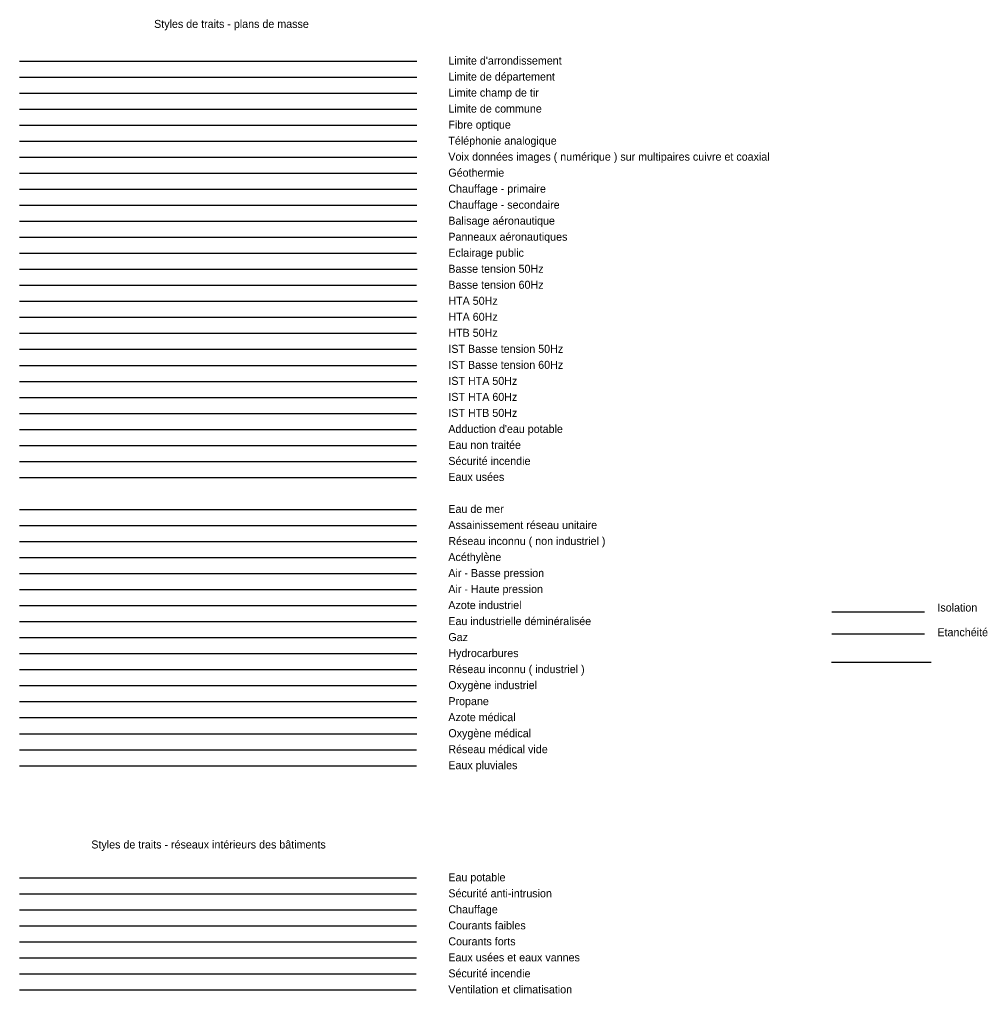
# Model space of a CAD drawing. Extents: x 3494.1 to 3554.6, y -18944.5 to -18883.7.
import ezdxf

# ---------------------------------------------------------------- set-up
doc = ezdxf.new("R2010")
doc.units = 0
for name, color, linetype in [('GO_COUVERTURE', 7, 'Continuous'), ('LIM_ADM ARRONDISSEMENT', 7, 'Continuous'), ('LIM_ADM DEPARTEMENT', 7, 'Continuous'), ('LIM_ADM_CHAMP TIR', 7, 'Continuous'), ('LIM_ADM_COMMUNE', 7, 'Continuous'), ('R_CF_FO_CANALISATION_CL_C', 7, 'Continuous'), ('R_CF_TEL_LIAISON_CL_C', 7, 'Continuous'), ('R_CF_VDI_LIAISON_CL_C', 7, 'Continuous'), ('R_CH_GEOTHERMIE_CANALISATION_CL_C', 7, 'Continuous'), ('R_CH_PRIM_CANALISATION_CL_C', 7, 'Continuous'), ('R_CH_SECOND_CANALISATION_CL_C', 7, 'Continuous'), ('R_ECLAIR_AERO_LIAISON_CL_C', 7, 'Continuous'), ('R_ECLAIR_PANNEAU_AERO_LIAISON_CL_C', 7, 'Continuous'), ('R_ECLAIR_PUB_LIAISON_CL_C', 7, 'Continuous'), ('R_ELEC_BT_50HZ_LIAISON_CL_C', 7, 'Continuous'), ('R_ELEC_BT_60HZ_LIAISON_CL_C', 7, 'Continuous'), ('R_ELEC_HTA_50HZ_LIAISON_CL_C', 7, 'Continuous'), ('R_ELEC_HTA_60HZ_LIAISON_CL_C', 7, 'Continuous'), ('R_ELEC_HTB_50HZ_LIAISON_CL_C', 7, 'Continuous'), ('R_ELEC_IST_BT_50HZ_LIAISON_CL_C', 7, 'Continuous'), ('R_ELEC_IST_BT_60HZ_LIAISON_CL_C', 7, 'Continuous'), ('R_ELEC_IST_HTA_50HZ_LIAISON_CL_C', 7, 'Continuous'), ('R_ELEC_IST_HTA_60HZ_LIAISON_CL_C', 7, 'Continuous'), ('R_ELEC_IST_HTB_50HZ_LIAISON_CL_C', 7, 'Continuous'), ('R_EPR_AEP_CANALISATION_CL_C', 7, 'Continuous'), ('R_EPR_EAU_NON_TRAITEE_CANALISATION_CL_C', 7, 'Continuous'), ('R_EPR_INCENDIE_CANALISATION_CL_C', 7, 'Continuous'), ('R_ES_EU_CANALISATION_CL_C', 7, 'Continuous'), ('R_ES_MER_CANALISATION_CL_C', 7, 'Continuous'), ('R_ES_UNITAIRE_CANALISATION_CL_C', 7, 'Continuous'), ('R_INCONNU_CANALISATION_CL_C', 7, 'Continuous'), ('R_IND_ACETYLENE_CANALISATION_CL_C', 7, 'Continuous'), ('R_IND_AIR_BP_CANALISATION_CL_C', 7, 'Continuous'), ('R_IND_AIR_HP_CANALISATION_CL_C', 7, 'Continuous'), ('R_IND_AZOTE_CANALISATION_CL_C', 7, 'Continuous'), ('R_IND_EAU_DEMINERALISEE_CANALISATION_CL_C', 7, 'Continuous'), ('R_IND_GAZ_NAT_CANALISATION_CL_C', 7, 'Continuous'), ('R_IND_HYDROCARBURE_CANALISATION_CL_C', 7, 'Continuous'), ('R_IND_INDUS_INCON_CANALISATION_CL_C', 7, 'Continuous'), ('R_IND_OXYGENE_CANALISATION_CL_C', 7, 'Continuous'), ('R_IND_PROPANE_CANALISATION_CL_C', 7, 'Continuous'), ('R_MED_AZOTE_CANALISATION_CL_C', 7, 'Continuous'), ('R_MED_OXYGENE_CANALISATION_CL_C', 7, 'Continuous'), ('R_MED_VIDE_CANALISATION_CL_C', 7, 'Continuous'), ('R_PLU_CANALISATION_CL_C', 7, 'Continuous'), ('SO_AEP_LIAISON', 7, 'Continuous'), ('SO_ANTI_INTRUSION_LIAISON', 7, 'Continuous'), ('SO_CHAUFFAGE_LIAISON', 7, 'Continuous'), ('SO_ELEC_C_FAIBLES_LIAISON', 7, 'Continuous'), ('SO_ELEC_C_FORTS_LIAISON', 7, 'Continuous'), ('SO_EU_EV_LIAISON', 7, 'Continuous'), ('SO_ISOLATION', 7, 'Continuous'), ('SO_SECU_INCENDIE_LIAISON', 7, 'Continuous'), ('SO_VMC_CVC_CTA_RES-TEXTE', 7, 'Continuous'), ('VOIRIE_VOIES FERREES', 7, 'Continuous')]:
    doc.layers.add(name, color=color, linetype=linetype)

msp = doc.modelspace()

# ---------------------------------------------------------------- linework, layer by layer
at = {"layer": 'GO_COUVERTURE'}
msp.add_line((3544.844, -18922.069), (3550.637, -18922.069), dxfattribs=at)
at = {"layer": 'LIM_ADM ARRONDISSEMENT'}
msp.add_line((3494.112, -18886.308), (3518.932, -18886.308), dxfattribs=at)
at = {"layer": 'LIM_ADM DEPARTEMENT'}
msp.add_line((3494.112, -18887.308), (3518.932, -18887.308), dxfattribs=at)
at = {"layer": 'LIM_ADM_CHAMP TIR'}
msp.add_line((3494.112, -18888.308), (3518.932, -18888.308), dxfattribs=at)
at = {"layer": 'LIM_ADM_COMMUNE'}
msp.add_line((3494.112, -18889.308), (3518.932, -18889.308), dxfattribs=at)
at = {"layer": 'R_CF_FO_CANALISATION_CL_C'}
msp.add_line((3494.112, -18890.308), (3518.932, -18890.308), dxfattribs=at)
at = {"layer": 'R_CF_TEL_LIAISON_CL_C'}
msp.add_line((3494.112, -18891.308), (3518.932, -18891.308), dxfattribs=at)
at = {"layer": 'R_CF_VDI_LIAISON_CL_C'}
msp.add_line((3494.112, -18892.308), (3518.932, -18892.308), dxfattribs=at)
at = {"layer": 'R_CH_GEOTHERMIE_CANALISATION_CL_C'}
msp.add_line((3494.112, -18893.308), (3518.932, -18893.308), dxfattribs=at)
at = {"layer": 'R_CH_PRIM_CANALISATION_CL_C'}
msp.add_line((3494.112, -18894.308), (3518.932, -18894.308), dxfattribs=at)
at = {"layer": 'R_CH_SECOND_CANALISATION_CL_C'}
msp.add_line((3494.112, -18895.308), (3518.932, -18895.308), dxfattribs=at)
at = {"layer": 'R_ECLAIR_AERO_LIAISON_CL_C'}
msp.add_line((3494.112, -18896.308), (3518.932, -18896.308), dxfattribs=at)
at = {"layer": 'R_ECLAIR_PANNEAU_AERO_LIAISON_CL_C'}
msp.add_line((3494.112, -18897.308), (3518.932, -18897.308), dxfattribs=at)
at = {"layer": 'R_ECLAIR_PUB_LIAISON_CL_C'}
msp.add_line((3494.112, -18898.308), (3518.912, -18898.308), dxfattribs=at)
at = {"layer": 'R_ELEC_BT_50HZ_LIAISON_CL_C'}
msp.add_line((3494.112, -18899.308), (3518.942, -18899.308), dxfattribs=at)
at = {"layer": 'R_ELEC_BT_60HZ_LIAISON_CL_C'}
msp.add_line((3494.112, -18900.308), (3518.905, -18900.308), dxfattribs=at)
at = {"layer": 'R_ELEC_HTA_50HZ_LIAISON_CL_C'}
msp.add_line((3494.112, -18901.308), (3518.95, -18901.308), dxfattribs=at)
at = {"layer": 'R_ELEC_HTA_60HZ_LIAISON_CL_C'}
msp.add_line((3494.112, -18902.308), (3518.905, -18902.308), dxfattribs=at)
at = {"layer": 'R_ELEC_HTB_50HZ_LIAISON_CL_C'}
msp.add_line((3494.112, -18903.304), (3518.905, -18903.304), dxfattribs=at)
at = {"layer": 'R_ELEC_IST_BT_50HZ_LIAISON_CL_C'}
msp.add_line((3494.112, -18904.308), (3518.897, -18904.308), dxfattribs=at)
at = {"layer": 'R_ELEC_IST_BT_60HZ_LIAISON_CL_C'}
msp.add_line((3494.112, -18905.308), (3518.912, -18905.308), dxfattribs=at)
at = {"layer": 'R_ELEC_IST_HTA_50HZ_LIAISON_CL_C'}
msp.add_line((3494.112, -18906.308), (3518.927, -18906.308), dxfattribs=at)
at = {"layer": 'R_ELEC_IST_HTA_60HZ_LIAISON_CL_C'}
msp.add_line((3494.112, -18907.308), (3518.927, -18907.308), dxfattribs=at)
at = {"layer": 'R_ELEC_IST_HTB_50HZ_LIAISON_CL_C'}
msp.add_line((3494.112, -18908.308), (3518.897, -18908.308), dxfattribs=at)
at = {"layer": 'R_EPR_AEP_CANALISATION_CL_C'}
msp.add_line((3494.112, -18909.308), (3518.897, -18909.308), dxfattribs=at)
at = {"layer": 'R_EPR_EAU_NON_TRAITEE_CANALISATION_CL_C'}
msp.add_line((3494.112, -18910.308), (3518.912, -18910.308), dxfattribs=at)
at = {"layer": 'R_EPR_INCENDIE_CANALISATION_CL_C'}
msp.add_line((3494.112, -18911.308), (3518.912, -18911.308), dxfattribs=at)
at = {"layer": 'R_ES_EU_CANALISATION_CL_C'}
msp.add_line((3494.112, -18912.308), (3518.897, -18912.308), dxfattribs=at)
at = {"layer": 'R_ES_MER_CANALISATION_CL_C'}
msp.add_line((3494.112, -18914.308), (3518.912, -18914.308), dxfattribs=at)
at = {"layer": 'R_ES_UNITAIRE_CANALISATION_CL_C'}
msp.add_line((3494.112, -18915.308), (3518.897, -18915.308), dxfattribs=at)
at = {"layer": 'R_INCONNU_CANALISATION_CL_C'}
msp.add_line((3494.112, -18916.308), (3518.927, -18916.308), dxfattribs=at)
at = {"layer": 'R_IND_ACETYLENE_CANALISATION_CL_C'}
msp.add_line((3494.112, -18917.308), (3518.883, -18917.308), dxfattribs=at)
at = {"layer": 'R_IND_AIR_BP_CANALISATION_CL_C'}
msp.add_line((3494.112, -18918.308), (3518.897, -18918.308), dxfattribs=at)
at = {"layer": 'R_IND_AIR_HP_CANALISATION_CL_C'}
msp.add_line((3494.112, -18919.308), (3518.912, -18919.308), dxfattribs=at)
at = {"layer": 'R_IND_AZOTE_CANALISATION_CL_C'}
msp.add_line((3494.112, -18920.308), (3518.912, -18920.308), dxfattribs=at)
at = {"layer": 'R_IND_EAU_DEMINERALISEE_CANALISATION_CL_C'}
msp.add_line((3494.112, -18921.308), (3518.912, -18921.308), dxfattribs=at)
at = {"layer": 'R_IND_GAZ_NAT_CANALISATION_CL_C'}
msp.add_line((3494.112, -18922.308), (3518.912, -18922.308), dxfattribs=at)
at = {"layer": 'R_IND_HYDROCARBURE_CANALISATION_CL_C'}
msp.add_line((3494.112, -18923.308), (3518.927, -18923.308), dxfattribs=at)
at = {"layer": 'R_IND_INDUS_INCON_CANALISATION_CL_C'}
msp.add_line((3494.112, -18924.308), (3518.927, -18924.308), dxfattribs=at)
at = {"layer": 'R_IND_OXYGENE_CANALISATION_CL_C'}
msp.add_line((3494.112, -18925.308), (3518.897, -18925.308), dxfattribs=at)
at = {"layer": 'R_IND_PROPANE_CANALISATION_CL_C'}
msp.add_line((3494.112, -18926.308), (3518.897, -18926.308), dxfattribs=at)
at = {"layer": 'R_MED_AZOTE_CANALISATION_CL_C'}
msp.add_line((3494.112, -18927.308), (3518.927, -18927.308), dxfattribs=at)
at = {"layer": 'R_MED_OXYGENE_CANALISATION_CL_C'}
msp.add_line((3494.112, -18928.308), (3518.927, -18928.308), dxfattribs=at)
at = {"layer": 'R_MED_VIDE_CANALISATION_CL_C'}
msp.add_line((3494.112, -18929.308), (3518.912, -18929.308), dxfattribs=at)
at = {"layer": 'R_PLU_CANALISATION_CL_C'}
msp.add_line((3494.112, -18930.308), (3518.912, -18930.308), dxfattribs=at)
at = {"layer": 'SO_AEP_LIAISON'}
msp.add_line((3494.112, -18937.308), (3518.912, -18937.308), dxfattribs=at)
at = {"layer": 'SO_ANTI_INTRUSION_LIAISON'}
msp.add_line((3494.112, -18938.308), (3518.912, -18938.308), dxfattribs=at)
at = {"layer": 'SO_CHAUFFAGE_LIAISON'}
msp.add_line((3494.112, -18939.308), (3518.912, -18939.308), dxfattribs=at)
at = {"layer": 'SO_ELEC_C_FAIBLES_LIAISON'}
msp.add_line((3494.112, -18940.308), (3518.912, -18940.308), dxfattribs=at)
at = {"layer": 'SO_ELEC_C_FORTS_LIAISON'}
msp.add_line((3494.112, -18941.308), (3518.897, -18941.308), dxfattribs=at)
at = {"layer": 'SO_EU_EV_LIAISON'}
msp.add_line((3494.112, -18942.308), (3518.897, -18942.308), dxfattribs=at)
at = {"layer": 'SO_ISOLATION'}
msp.add_line((3544.844, -18920.705), (3550.637, -18920.705), dxfattribs=at)
at = {"layer": 'SO_SECU_INCENDIE_LIAISON'}
msp.add_line((3494.112, -18943.308), (3518.883, -18943.308), dxfattribs=at)
at = {"layer": 'SO_VMC_CVC_CTA_RES-TEXTE'}
msp.add_line((3494.112, -18944.308), (3518.883, -18944.308), dxfattribs=at)
at = {"layer": 'VOIRIE_VOIES FERREES'}
msp.add_line((3544.823, -18923.85), (3551.054, -18923.85), dxfattribs=at)

# ---------------------------------------------------------------- texts
at = {"layer": 'GO_COUVERTURE'}
msp.add_text('Etanchéité', height=0.5, dxfattribs=at).set_placement((3551.437, -18922.223))
at = {"layer": 'LIM_ADM ARRONDISSEMENT'}
msp.add_text("Limite d'arrondissement", height=0.5, dxfattribs=at).set_placement((3520.895, -18886.527))
at = {"layer": 'LIM_ADM DEPARTEMENT'}
msp.add_text('Limite de département', height=0.5, dxfattribs=at).set_placement((3520.895, -18887.527))
at = {"layer": 'LIM_ADM_CHAMP TIR'}
msp.add_text('Limite champ de tir', height=0.5, dxfattribs=at).set_placement((3520.895, -18888.527))
at = {"layer": 'LIM_ADM_COMMUNE'}
msp.add_text('Limite de commune', height=0.5, dxfattribs=at).set_placement((3520.895, -18889.527))
at = {"layer": 'R_CF_FO_CANALISATION_CL_C'}
msp.add_text('Fibre optique', height=0.5, dxfattribs=at).set_placement((3520.895, -18890.527))
at = {"layer": 'R_CF_TEL_LIAISON_CL_C'}
msp.add_text('Téléphonie analogique', height=0.5, dxfattribs=at).set_placement((3520.895, -18891.527))
at = {"layer": 'R_CF_VDI_LIAISON_CL_C'}
msp.add_text('Voix données images ( numérique ) sur multipaires cuivre et coaxial', height=0.5, dxfattribs=at).set_placement((3520.895, -18892.527))
at = {"layer": 'R_CH_GEOTHERMIE_CANALISATION_CL_C'}
msp.add_text('Géothermie', height=0.5, dxfattribs=at).set_placement((3520.895, -18893.527))
at = {"layer": 'R_CH_PRIM_CANALISATION_CL_C'}
msp.add_text('Chauffage - primaire', height=0.5, dxfattribs=at).set_placement((3520.895, -18894.527))
at = {"layer": 'R_CH_SECOND_CANALISATION_CL_C'}
msp.add_text('Chauffage - secondaire ', height=0.5, dxfattribs=at).set_placement((3520.895, -18895.527))
at = {"layer": 'R_ECLAIR_AERO_LIAISON_CL_C'}
msp.add_text('Balisage aéronautique', height=0.5, dxfattribs=at).set_placement((3520.895, -18896.527))
at = {"layer": 'R_ECLAIR_PANNEAU_AERO_LIAISON_CL_C'}
msp.add_text('Panneaux aéronautiques', height=0.5, dxfattribs=at).set_placement((3520.895, -18897.527))
at = {"layer": 'R_ECLAIR_PUB_LIAISON_CL_C'}
msp.add_text('Eclairage public', height=0.5, dxfattribs=at).set_placement((3520.895, -18898.527))
at = {"layer": 'R_ELEC_BT_50HZ_LIAISON_CL_C'}
msp.add_text('Basse tension 50Hz', height=0.5, dxfattribs=at).set_placement((3520.895, -18899.527))
at = {"layer": 'R_ELEC_BT_60HZ_LIAISON_CL_C'}
msp.add_text('Basse tension 60Hz', height=0.5, dxfattribs=at).set_placement((3520.895, -18900.527))
at = {"layer": 'R_ELEC_HTA_50HZ_LIAISON_CL_C'}
msp.add_text('HTA 50Hz', height=0.5, dxfattribs=at).set_placement((3520.895, -18901.527))
at = {"layer": 'R_ELEC_HTA_60HZ_LIAISON_CL_C'}
msp.add_text('HTA 60Hz', height=0.5, dxfattribs=at).set_placement((3520.895, -18902.527))
at = {"layer": 'R_ELEC_HTB_50HZ_LIAISON_CL_C'}
msp.add_text('HTB 50Hz', height=0.5, dxfattribs=at).set_placement((3520.895, -18903.527))
at = {"layer": 'R_ELEC_IST_BT_50HZ_LIAISON_CL_C'}
msp.add_text('IST Basse tension 50Hz', height=0.5, dxfattribs=at).set_placement((3520.895, -18904.527))
at = {"layer": 'R_ELEC_IST_BT_60HZ_LIAISON_CL_C'}
msp.add_text('IST Basse tension 60Hz', height=0.5, dxfattribs=at).set_placement((3520.895, -18905.527))
at = {"layer": 'R_ELEC_IST_HTA_50HZ_LIAISON_CL_C'}
msp.add_text('IST HTA 50Hz', height=0.5, dxfattribs=at).set_placement((3520.895, -18906.527))
at = {"layer": 'R_ELEC_IST_HTA_60HZ_LIAISON_CL_C'}
msp.add_text('IST HTA 60Hz', height=0.5, dxfattribs=at).set_placement((3520.895, -18907.527))
at = {"layer": 'R_ELEC_IST_HTB_50HZ_LIAISON_CL_C'}
msp.add_text('IST HTB 50Hz', height=0.5, dxfattribs=at).set_placement((3520.895, -18908.527))
at = {"layer": 'R_EPR_AEP_CANALISATION_CL_C'}
msp.add_text("Adduction d'eau potable ", height=0.5, dxfattribs=at).set_placement((3520.895, -18909.527))
at = {"layer": 'R_EPR_EAU_NON_TRAITEE_CANALISATION_CL_C'}
msp.add_text('Eau non traitée', height=0.5, dxfattribs=at).set_placement((3520.895, -18910.527))
at = {"layer": 'R_EPR_INCENDIE_CANALISATION_CL_C'}
msp.add_text('Sécurité incendie', height=0.5, dxfattribs=at).set_placement((3520.895, -18911.527))
at = {"layer": 'R_ES_EU_CANALISATION_CL_C'}
msp.add_text('Eaux usées', height=0.5, dxfattribs=at).set_placement((3520.895, -18912.527))
at = {"layer": 'R_ES_MER_CANALISATION_CL_C'}
msp.add_text('Eau de mer', height=0.5, dxfattribs=at).set_placement((3520.895, -18914.527))
at = {"layer": 'R_ES_UNITAIRE_CANALISATION_CL_C'}
msp.add_text('Assainissement réseau unitaire', height=0.5, dxfattribs=at).set_placement((3520.895, -18915.527))
at = {"layer": 'R_INCONNU_CANALISATION_CL_C'}
msp.add_text('Réseau inconnu ( non industriel )', height=0.5, dxfattribs=at).set_placement((3520.895, -18916.527))
at = {"layer": 'R_IND_ACETYLENE_CANALISATION_CL_C'}
msp.add_text('Acéthylène', height=0.5, dxfattribs=at).set_placement((3520.895, -18917.527))
at = {"layer": 'R_IND_AIR_BP_CANALISATION_CL_C'}
msp.add_text('Air - Basse pression', height=0.5, dxfattribs=at).set_placement((3520.895, -18918.527))
at = {"layer": 'R_IND_AIR_HP_CANALISATION_CL_C'}
msp.add_text('Air - Haute pression', height=0.5, dxfattribs=at).set_placement((3520.895, -18919.527))
at = {"layer": 'R_IND_AZOTE_CANALISATION_CL_C'}
msp.add_text('Azote industriel', height=0.5, dxfattribs=at).set_placement((3520.895, -18920.527))
at = {"layer": 'R_IND_EAU_DEMINERALISEE_CANALISATION_CL_C'}
msp.add_text('Eau industrielle déminéralisée', height=0.5, dxfattribs=at).set_placement((3520.895, -18921.527))
at = {"layer": 'R_IND_GAZ_NAT_CANALISATION_CL_C'}
msp.add_text('Gaz', height=0.5, dxfattribs=at).set_placement((3520.895, -18922.527))
at = {"layer": 'R_IND_HYDROCARBURE_CANALISATION_CL_C'}
msp.add_text('Hydrocarbures', height=0.5, dxfattribs=at).set_placement((3520.895, -18923.527))
at = {"layer": 'R_IND_INDUS_INCON_CANALISATION_CL_C'}
msp.add_text('Réseau inconnu ( industriel )', height=0.5, dxfattribs=at).set_placement((3520.895, -18924.527))
at = {"layer": 'R_IND_OXYGENE_CANALISATION_CL_C'}
msp.add_text('Oxygène industriel', height=0.5, dxfattribs=at).set_placement((3520.895, -18925.527))
at = {"layer": 'R_IND_PROPANE_CANALISATION_CL_C'}
msp.add_text('Propane', height=0.5, dxfattribs=at).set_placement((3520.895, -18926.527))
at = {"layer": 'R_MED_AZOTE_CANALISATION_CL_C'}
msp.add_text('Azote médical', height=0.5, dxfattribs=at).set_placement((3520.895, -18927.527))
at = {"layer": 'R_MED_OXYGENE_CANALISATION_CL_C'}
msp.add_text('Oxygène médical', height=0.5, dxfattribs=at).set_placement((3520.895, -18928.527))
at = {"layer": 'R_MED_VIDE_CANALISATION_CL_C'}
msp.add_text('Réseau médical vide', height=0.5, dxfattribs=at).set_placement((3520.895, -18929.527))
at = {"layer": 'R_PLU_CANALISATION_CL_C'}
msp.add_text('Eaux pluviales', height=0.5, dxfattribs=at).set_placement((3520.895, -18930.527))
at = {"layer": 'SO_AEP_LIAISON'}
msp.add_text('Eau potable', height=0.5, dxfattribs=at).set_placement((3520.895, -18937.527))
at = {"layer": 'SO_ANTI_INTRUSION_LIAISON'}
msp.add_text('Sécurité anti-intrusion', height=0.5, dxfattribs=at).set_placement((3520.895, -18938.527))
at = {"layer": 'SO_CHAUFFAGE_LIAISON'}
msp.add_text('Chauffage', height=0.5, dxfattribs=at).set_placement((3520.895, -18939.527))
at = {"layer": 'SO_ELEC_C_FAIBLES_LIAISON'}
msp.add_text('Courants faibles', height=0.5, dxfattribs=at).set_placement((3520.895, -18940.527))
at = {"layer": 'SO_ELEC_C_FORTS_LIAISON'}
msp.add_text('Courants forts', height=0.5, dxfattribs=at).set_placement((3520.895, -18941.527))
at = {"layer": 'SO_EU_EV_LIAISON'}
msp.add_text('Eaux usées et eaux vannes', height=0.5, dxfattribs=at).set_placement((3520.895, -18942.527))
at = {"layer": 'SO_ISOLATION'}
msp.add_text('Isolation', height=0.5, dxfattribs=at).set_placement((3551.437, -18920.682))
at = {"layer": 'SO_SECU_INCENDIE_LIAISON'}
msp.add_text('Sécurité incendie', height=0.5, dxfattribs=at).set_placement((3520.895, -18943.527))
at = {"layer": 'SO_VMC_CVC_CTA_RES-TEXTE'}
for s, p in [('Styles de traits - plans de masse', (3502.52, -18884.237)), ('Styles de traits - réseaux intérieurs des bâtiments', (3498.597, -18935.478)), ('Ventilation et climatisation', (3520.895, -18944.527))]:
    msp.add_text(s, height=0.5, dxfattribs=at).set_placement(p)

doc.saveas('drawing.dxf')
